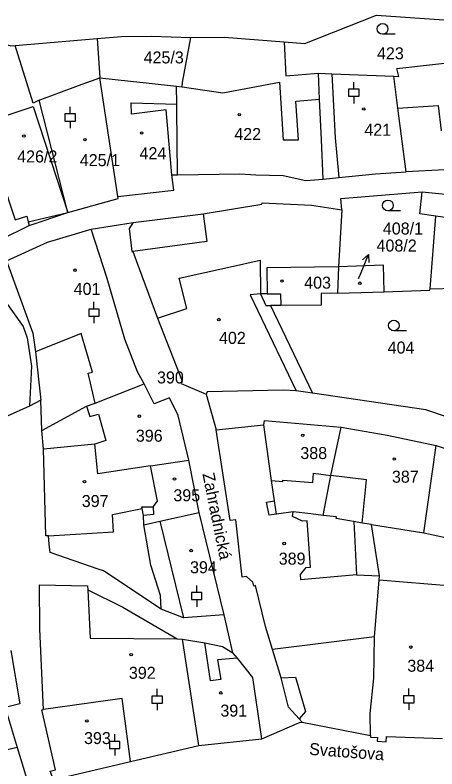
# Model space of a CAD drawing. Extents: x -737240 to -735272, y -1119606 to -1117878.
# Drawn here: x -736084.7 to -736024.9, y -1119478 to -1119371.4 of the extents above; entities that cross this region are included whole.
import ezdxf

# ---------------------------------------------------------------- set-up
doc = ezdxf.new("R2010")
doc.units = 0
for name, color, linetype in [('Level 1', 7, 'Continuous'), ('Level 15', 7, 'Continuous'), ('Level 16', 7, 'Continuous'), ('Level 18', 7, 'Continuous'), ('Level 19', 7, 'Continuous'), ('Level 25', 7, 'Continuous'), ('Level 4', 7, 'Continuous')]:
    doc.layers.add(name, color=color, linetype=linetype)

msp = doc.modelspace()

# ---------------------------------------------------------------- linework, layer by layer
at = {"layer": 'Level 1'}
for p, q in [((-736084.65, -1119375.65), (-736073.07, -1119374.67)), ((-736073.07, -1119374.67), (-736072.68, -1119380.23)), ((-736041.73, -1119379.58), (-736039.83, -1119379.66)), ((-736041.56, -1119383.28), (-736041.73, -1119379.58)), ((-736070.15, -1119397.05), (-736072.68, -1119380.23)), ((-736039.83, -1119379.66), (-736031.06, -1119380.02)), ((-736030.48, -1119384.55), (-736031.06, -1119380.02)), ((-736061.8, -1119383.96), (-736061.83, -1119381.42)), ((-736061.83, -1119381.42), (-736061.04, -1119381.53)), ((-736077.23, -1119399.29), (-736081.29, -1119383.4)), ((-736029.32, -1119393.53), (-736030.48, -1119384.55)), ((-736062.47, -1119393.97), (-736061.69, -1119393.96)), ((-736041.05, -1119394.6), (-736038.82, -1119394.34)), ((-736082.68, -1119401.14), (-736077.23, -1119399.29)), ((-736067.94, -1119400.7), (-736058.04, -1119399.48)), ((-736038.41, -1119398.94), (-736038.9, -1119406.97)), ((-736025.92, -1119410.1), (-736025.11, -1119399.83)), ((-736082.82, -1119400.63), (-736082.68, -1119401.14)), ((-736073.89, -1119401.66), (-736067.94, -1119400.7)), ((-736068.03, -1119404.81), (-736064.52, -1119414.26)), ((-736038.9, -1119406.97), (-736039.04, -1119410.73)), ((-736049, -1119410.79), (-736049.95, -1119410.8)), ((-736039.04, -1119410.73), (-736032.41, -1119410.51)), ((-736047.06, -1119412.43), (-736048.5, -1119412.44)), ((-736048.5, -1119412.44), (-736042.57, -1119424.85)), ((-736081.78, -1119418.99), (-736081.03, -1119425.85)), ((-736073.34, -1119426.29), (-736066.39, -1119423.52)), ((-736057.61, -1119424.98), (-736056.23, -1119430.06)), ((-736042.57, -1119424.85), (-736044.86, -1119424.51)), ((-736081.03, -1119425.85), (-736082.65, -1119426.67)), ((-736080.9, -1119430.13), (-736081.03, -1119425.85)), ((-736074.56, -1119426.69), (-736073.34, -1119426.29)), ((-736082.65, -1119426.67), (-736090.01, -1119429.97)), ((-736080.9, -1119430.13), (-736074.56, -1119426.69)), ((-736056.23, -1119430.06), (-736049.48, -1119429.31)), ((-736039.98, -1119436.48), (-736038.5, -1119429.65)), ((-736080.67, -1119432.79), (-736080.9, -1119430.13)), ((-736073.38, -1119432.07), (-736080.67, -1119432.79)), ((-736026.81, -1119444.6), (-736025.04, -1119432.26)), ((-736025.04, -1119432.26), (-736013.53, -1119436.23)), ((-736065.52, -1119435.13), (-736060.1, -1119434.31)), ((-736058.62, -1119441.71), (-736060.1, -1119434.31)), ((-736041.04, -1119442.14), (-736039.98, -1119436.48)), ((-736047.94, -1119440.09), (-736048.35, -1119437.22)), ((-736047.67, -1119441.96), (-736047.94, -1119440.09)), ((-736066.52, -1119442.18), (-736066.68, -1119441.16)), ((-736066.43, -1119443.48), (-736066.52, -1119442.18)), ((-736064.2, -1119442.97), (-736058.62, -1119441.71)), ((-736055.07, -1119456.2), (-736058.62, -1119441.71)), ((-736045.29, -1119441.63), (-736047.67, -1119441.96)), ((-736066.43, -1119443.48), (-736064.2, -1119442.97)), ((-736035.54, -1119443.22), (-736036.7, -1119443.02)), ((-736034.22, -1119443.45), (-736035.54, -1119443.22)), ((-736034.22, -1119443.45), (-736026.81, -1119444.6)), ((-736033.09, -1119450.68), (-736034.22, -1119443.45)), ((-736026.81, -1119444.6), (-736017.07, -1119446.68)), ((-736033.14, -1119451.24), (-736033.09, -1119450.68)), ((-736033.8, -1119459.33), (-736033.14, -1119451.24)), ((-736033.14, -1119451.24), (-736022.77, -1119452.11)), ((-736060.82, -1119456.62), (-736064, -1119455.39)), ((-736055.07, -1119456.2), (-736060.82, -1119456.62)), ((-736053.87, -1119461.59), (-736055.07, -1119456.2)), ((-736061.74, -1119459.59), (-736060.97, -1119459.67)), ((-736058.67, -1119474.71), (-736060.97, -1119459.67)), ((-736060.97, -1119459.67), (-736057.81, -1119460.16)), ((-736053.2, -1119462.35), (-736053.87, -1119461.59)), ((-736046.99, -1119465.13), (-736048.21, -1119461.12)), ((-736044.03, -1119471.37), (-736044.45, -1119470.92)), ((-736044.03, -1119471.37), (-736034.34, -1119473.29)), ((-736058.67, -1119474.71), (-736049.73, -1119473.75)), ((-736084.37, -1119474.98), (-736089.13, -1119476.09)), ((-736068.32, -1119476.96), (-736058.67, -1119474.71))]:
    msp.add_line(p, q, dxfattribs=at)
for points in [[(-736046.57, -1119375.17), (-736043.65, -1119375.41), (-736033.49, -1119371.37), (-736023.98, -1119372.04), (-736014.53, -1119371.45), (-736013.76, -1119377.04)], [(-736087.52, -1119375.07), (-736085.3, -1119375.7), (-736084.65, -1119375.65)], [(-736073.07, -1119374.67), (-736069.61, -1119374.38), (-736065.36, -1119374.33), (-736059.78, -1119374.52)], [(-736061.04, -1119381.53), (-736060.96, -1119380.9), (-736059.78, -1119374.52)], [(-736059.78, -1119374.52), (-736055.07, -1119374.48), (-736046.57, -1119375.17)], [(-736046.57, -1119375.17), (-736046.35, -1119379.95), (-736041.73, -1119379.58)], [(-736081.29, -1119383.4), (-736082.1, -1119383.85), (-736084.65, -1119375.65)], [(-736031.06, -1119380.02), (-736030.33, -1119380.05), (-736030.61, -1119378.91), (-736013.76, -1119377.04)], [(-736072.68, -1119380.23), (-736068.32, -1119380.7), (-736066.14, -1119380.94), (-736061.83, -1119381.42)], [(-736041.05, -1119394.6), (-736041.3, -1119389.02), (-736041.56, -1119383.28)], [(-736061.69, -1119393.96), (-736061.79, -1119384.61), (-736061.8, -1119383.96)], [(-736030.48, -1119384.55), (-736024.79, -1119384.14), (-736024.37, -1119387.75)], [(-736015.35, -1119393.23), (-736017.32, -1119393.07), (-736018.21, -1119393.1), (-736021.7, -1119393.2), (-736023.88, -1119393.27), (-736029.32, -1119393.53)], [(-736086.6, -1119394.48), (-736084.67, -1119400.35), (-736083.03, -1119399.83), (-736082.82, -1119400.63)], [(-736070.15, -1119397.05), (-736062.22, -1119396.15), (-736062.47, -1119393.97)], [(-736061.69, -1119393.96), (-736052.88, -1119393.85), (-736050.58, -1119393.95), (-736046.73, -1119394.06), (-736043.51, -1119394.77), (-736041.05, -1119394.6)], [(-736038.82, -1119394.34), (-736033.66, -1119393.83), (-736029.32, -1119393.53)], [(-736038.41, -1119398.94), (-736038.55, -1119397.32), (-736027.03, -1119396.36)], [(-736025.11, -1119399.83), (-736027.35, -1119399.5), (-736027.03, -1119396.36)], [(-736027.03, -1119396.36), (-736022.77, -1119396.8), (-736009.67, -1119398.12)], [(-736077.23, -1119399.29), (-736070.11, -1119397.3), (-736070.15, -1119397.05)], [(-736058.04, -1119399.48), (-736049.72, -1119398.12), (-736049.71, -1119397.91), (-736042.73, -1119398.26), (-736038.41, -1119398.94)], [(-736067.94, -1119400.7), (-736068.53, -1119401.55), (-736068.16, -1119404.83), (-736068.03, -1119404.81)], [(-736093.38, -1119406.39), (-736086.72, -1119403.1), (-736082.68, -1119401.14)], [(-736085.92, -1119406.12), (-736080.08, -1119403.47), (-736073.89, -1119401.66)], [(-736066.39, -1119423.52), (-736067.35, -1119421.82), (-736069.12, -1119417.23), (-736071.66, -1119408.61), (-736073.89, -1119401.66)], [(-736085.92, -1119406.12), (-736082.17, -1119416.37), (-736081.78, -1119418.99)], [(-736038.9, -1119406.97), (-736049.03, -1119407.14), (-736049, -1119410.79)], [(-736032.41, -1119410.51), (-736032.53, -1119406.75), (-736038.9, -1119406.97)], [(-736088.59, -1119408.39), (-736083.52, -1119415.42), (-736082.96, -1119417.03), (-736082.38, -1119421.04), (-736082.65, -1119426.67)], [(-736032.41, -1119410.51), (-736025.94, -1119410.3), (-736025.92, -1119410.1)], [(-736025.92, -1119410.1), (-736022.38, -1119409.98), (-736018.9, -1119410.43)], [(-736049.95, -1119410.8), (-736049.17, -1119412.44), (-736048.5, -1119412.44)], [(-736039.04, -1119410.73), (-736041.34, -1119410.74), (-736041.33, -1119412.41), (-736047.06, -1119412.43)], [(-736064.52, -1119414.26), (-736061.03, -1119423.17), (-736061.18, -1119423.5), (-736057.61, -1119424.98)], [(-736060.1, -1119434.31), (-736061.59, -1119428.01), (-736062.81, -1119425.5), (-736064.97, -1119426.34), (-736066.39, -1119423.52)], [(-736044.86, -1119424.51), (-736046.7, -1119424.42), (-736057.46, -1119424.66), (-736057.61, -1119424.98)], [(-736020.68, -1119429.21), (-736026.5, -1119427.23), (-736042.57, -1119424.85)], [(-736049.48, -1119429.31), (-736049.38, -1119428.7), (-736038.5, -1119429.65)], [(-736048.35, -1119437.22), (-736048.64, -1119435.2), (-736049.48, -1119429.31)], [(-736038.5, -1119429.65), (-736032.01, -1119430.78), (-736025.04, -1119432.26)], [(-736048.21, -1119461.12), (-736049.2, -1119457.87), (-736050.65, -1119452.07), (-736050.88, -1119452.13), (-736051.02, -1119451.59), (-736051.92, -1119450.8), (-736052.52, -1119450.87), (-736053.42, -1119442.76), (-736054.24, -1119442.85), (-736056.23, -1119430.06)], [(-736079.93, -1119445.05), (-736080.31, -1119445.01), (-736080.67, -1119432.79)], [(-736065.52, -1119435.13), (-736072.96, -1119436.25), (-736073.38, -1119432.07)], [(-736065.13, -1119440.92), (-736064.52, -1119440.14), (-736065.52, -1119435.13)], [(-736066.68, -1119441.16), (-736066.73, -1119440.93), (-736065.13, -1119440.92)], [(-736041.04, -1119442.14), (-736042.8, -1119441.93), (-736045.29, -1119441.63)], [(-736036.7, -1119443.02), (-736037.35, -1119442.91), (-736039.23, -1119442.58), (-736039.19, -1119442.36), (-736041.04, -1119442.14)], [(-736064, -1119455.39), (-736064.11, -1119453.45), (-736065.44, -1119449.17), (-736066.43, -1119443.48)], [(-736064, -1119455.39), (-736072.14, -1119449.97), (-736072.94, -1119449.73), (-736079.71, -1119447.37), (-736079.88, -1119446.21), (-736079.93, -1119445.05)], [(-736080.68, -1119469.61), (-736081.18, -1119458.22), (-736081.25, -1119451.98), (-736074.41, -1119452.12), (-736074.38, -1119452.65)], [(-736074.38, -1119452.65), (-736069.44, -1119455.11), (-736061.74, -1119459.59)], [(-736034.34, -1119473.29), (-736034.41, -1119470.16), (-736033.9, -1119465.19), (-736033.8, -1119459.33)], [(-736057.81, -1119460.16), (-736055.32, -1119460.71), (-736053.87, -1119461.59)], [(-736085.27, -1119461.24), (-736083.99, -1119468.81), (-736086.1, -1119469.33), (-736084.37, -1119474.98)], [(-736049.73, -1119473.75), (-736051.01, -1119465.06), (-736053.2, -1119462.35)], [(-736044.45, -1119470.92), (-736045.95, -1119469.27), (-736046.99, -1119465.13)], [(-736068.32, -1119476.96), (-736069.54, -1119468.04), (-736080.68, -1119469.61)], [(-736079, -1119480.18), (-736079.73, -1119478.33), (-736078.94, -1119478.12), (-736080.88, -1119469.64), (-736080.68, -1119469.61)], [(-736049.73, -1119473.75), (-736044.4, -1119471.45), (-736044.03, -1119471.37)], [(-736034.34, -1119473.29), (-736034.33, -1119473.53), (-736033.38, -1119473.55), (-736033.39, -1119474.07), (-736032.14, -1119474.17), (-736032.11, -1119473.43), (-736024.17, -1119473.71)], [(-736084.37, -1119474.98), (-736082.69, -1119480.52), (-736080.98, -1119484.97)], [(-736079, -1119480.18), (-736077.13, -1119480.13), (-736077.35, -1119479.08), (-736068.32, -1119476.96)]]:
    msp.add_lwpolyline(points, dxfattribs=at)
at = {"layer": 'Level 16'}
for points in [[(-736036.03, -1119408.61), (-736035.79, -1119408.02), (-736034.653, -1119405.244)], [(-736035.495, -1119405.98), (-736034.653, -1119405.244), (-736034.569, -1119406.359)]]:
    msp.add_lwpolyline(points, dxfattribs=at)
at = {"layer": 'Level 25'}
for p, q in [((-736030.858, -1119374.08), (-736032.64, -1119374.08)), ((-736036.73, -1119381.86), (-736036.73, -1119380.86)), ((-736036.73, -1119382.86), (-736036.73, -1119383.86)), ((-736076.87, -1119385.36), (-736076.87, -1119384.36)), ((-736076.87, -1119386.36), (-736076.87, -1119387.36)), ((-736030.108, -1119399.05), (-736031.89, -1119399.05)), ((-736073.51, -1119412.95), (-736073.51, -1119411.95)), ((-736073.51, -1119413.95), (-736073.51, -1119414.95)), ((-736029.268, -1119416.03), (-736031.05, -1119416.03)), ((-736058.97, -1119453.06), (-736058.97, -1119452.06)), ((-736058.97, -1119454.06), (-736058.97, -1119455.06)), ((-736064.57, -1119467.69), (-736064.57, -1119466.69)), ((-736028.94, -1119467.65), (-736028.94, -1119466.65)), ((-736064.57, -1119468.69), (-736064.57, -1119469.69)), ((-736028.94, -1119468.65), (-736028.94, -1119469.65)), ((-736070.58, -1119474.11), (-736070.58, -1119473.11)), ((-736070.58, -1119475.11), (-736070.58, -1119476.11))]:
    msp.add_line(p, q, dxfattribs=at)
for points in [[(-736037.48, -1119382.86), (-736035.98, -1119382.86), (-736035.98, -1119381.86), (-736037.48, -1119381.86)], [(-736077.62, -1119386.36), (-736076.12, -1119386.36), (-736076.12, -1119385.36), (-736077.62, -1119385.36)], [(-736074.26, -1119413.95), (-736072.76, -1119413.95), (-736072.76, -1119412.95), (-736074.26, -1119412.95)], [(-736059.72, -1119454.06), (-736058.22, -1119454.06), (-736058.22, -1119453.06), (-736059.72, -1119453.06)], [(-736065.32, -1119468.69), (-736063.82, -1119468.69), (-736063.82, -1119467.69), (-736065.32, -1119467.69)], [(-736029.69, -1119468.65), (-736028.19, -1119468.65), (-736028.19, -1119467.65), (-736029.69, -1119467.65)], [(-736071.33, -1119475.11), (-736069.83, -1119475.11), (-736069.83, -1119474.11), (-736071.33, -1119474.11)]]:
    msp.add_lwpolyline(points, close=True, dxfattribs=at)
for centre, major_axis, ratio in [((-736032.64, -1119373.324), (0.764, 0), 0.9894236), ((-736035.31, -1119384.65), (0.18, 0), 0.9848078), ((-736052.93, -1119385.45), (0.18, 0), 0.9848078), ((-736066.76, -1119388.05), (0.18, 0), 0.9848078), ((-736083.45, -1119388.48), (0.18, 0), 0.9848078), ((-736074.79, -1119389), (0.18, 0), 0.9848078), ((-736031.89, -1119398.294), (0.764, 0), 0.9894236), ((-736076.2, -1119407.46), (0.18, 0), 0.9848078), ((-736046.89, -1119408.99), (0.18, 0), 0.9848078), ((-736035.87, -1119409.3), (0.18, 0), 0.9848078), ((-736055.83, -1119414.44), (0.18, 0), 0.9848078), ((-736031.05, -1119415.274), (0.764, 0), 0.9894236), ((-736067.09, -1119428.1), (0.18, 0), 0.9848078), ((-736043.95, -1119430.82), (0.18, 0), 0.9848078), ((-736030.98, -1119434.17), (0.18, 0), 0.9848078), ((-736062.1, -1119437), (0.18, 0), 0.9848078), ((-736074.86, -1119437.37), (0.18, 0), 0.9848078), ((-736046.57, -1119446.12), (0.18, 0), 0.9848078), ((-736059.75, -1119447.12), (0.18, 0), 0.9848078), ((-736028.65, -1119460.77), (0.18, 0), 0.9848078), ((-736068.24, -1119461.85), (0.18, 0), 0.9848078), ((-736055.56, -1119467.25), (0.18, 0), 0.9848078), ((-736074.53, -1119471.22), (0.18, 0), 0.9848078)]:
    msp.add_ellipse(centre, major_axis=major_axis, ratio=ratio, dxfattribs=at)
at = {"layer": 'Level 4'}
for p, q in [((-736082.82, -1119400.63), (-736077.23, -1119399.29)), ((-736064.2, -1119442.97), (-736060.82, -1119456.62)), ((-736036.7, -1119443.02), (-736036.35, -1119450.53)), ((-736036.35, -1119450.53), (-736033.09, -1119450.68)), ((-736033.8, -1119459.33), (-736048.21, -1119461.12))]:
    msp.add_line(p, q, dxfattribs=at)
for points in [[(-736081.29, -1119383.4), (-736075.72, -1119381.35), (-736072.68, -1119380.23)], [(-736039.83, -1119379.66), (-736039.38, -1119388.72), (-736038.82, -1119394.34)], [(-736061.04, -1119381.53), (-736055.26, -1119382.38), (-736047.23, -1119380.86), (-736046.71, -1119389.01), (-736044.54, -1119389.01), (-736044.94, -1119383.53), (-736041.56, -1119383.28)], [(-736062.47, -1119393.97), (-736063.29, -1119384.79), (-736068.2, -1119385.39), (-736068.24, -1119383.77), (-736061.8, -1119383.96)], [(-736086.84, -1119386.04), (-736085.94, -1119385.58), (-736082.12, -1119384.32), (-736077.23, -1119399.29)], [(-736058.04, -1119399.48), (-736057.52, -1119403.41), (-736068.03, -1119404.81)], [(-736016.28, -1119410.77), (-736015.93, -1119407.73), (-736023.83, -1119406.91), (-736023.12, -1119400.12), (-736025.11, -1119399.83)], [(-736064.52, -1119414.26), (-736060.35, -1119412.86), (-736061.47, -1119408.57), (-736054.17, -1119406.97), (-736050, -1119406.06), (-736049.95, -1119410.8)], [(-736049.95, -1119410.8), (-736051.39, -1119410.93), (-736044.86, -1119424.51)], [(-736049, -1119410.79), (-736047.08, -1119410.78), (-736047.06, -1119412.43)], [(-736073.34, -1119426.29), (-736074.34, -1119422.02), (-736073.7, -1119421.87), (-736075.34, -1119416.4), (-736081.78, -1119418.99)], [(-736074.56, -1119426.69), (-736074.09, -1119428.17), (-736072.89, -1119427.82), (-736071.81, -1119431.56), (-736073.38, -1119432.07)], [(-736048.35, -1119437.22), (-736046.77, -1119437.34), (-736046.76, -1119437.18), (-736042.53, -1119437.5), (-736042.43, -1119436.18), (-736039.98, -1119436.48)], [(-736035.54, -1119443.22), (-736034.94, -1119437.11), (-736039.98, -1119436.48)], [(-736047.67, -1119441.96), (-736048.72, -1119442.11), (-736049.08, -1119440.25), (-736047.94, -1119440.09)], [(-736079.93, -1119445.05), (-736070.75, -1119444.49), (-736070.88, -1119442), (-736066.68, -1119441.16)], [(-736065.13, -1119440.92), (-736065.06, -1119442.01), (-736066.52, -1119442.18)], [(-736036.35, -1119450.53), (-736044.22, -1119451.24), (-736044.27, -1119450.52), (-736043.45, -1119449.53), (-736042.83, -1119449.47), (-736043.33, -1119442.89), (-736043.98, -1119442.94), (-736045.38, -1119442.29), (-736045.29, -1119441.63)], [(-736074.38, -1119452.65), (-736074.04, -1119459.52), (-736061.74, -1119459.59)], [(-736053.2, -1119462.35), (-736056.04, -1119462.57), (-736055.56, -1119465.36), (-736057.02, -1119465.54), (-736057.81, -1119460.16)], [(-736046.99, -1119465.13), (-736044.98, -1119465.03), (-736043.54, -1119469.86), (-736044.45, -1119470.92)]]:
    msp.add_lwpolyline(points, dxfattribs=at)

# ---------------------------------------------------------------- texts
at = {"layer": 'Level 15'}
for s, rotation, p in [('Zahradnická', 281.43144, (-736058.163, -1119436.272)), ('Svatošova', 355.75938, (-736043.085, -1119476.003))]:
    msp.add_text(s, height=1.7, rotation=rotation, dxfattribs=at).set_placement(p)
at = {"layer": 'Level 16'}
msp.add_text('408/2', height=1.7, dxfattribs=at).set_placement((-736033.495, -1119404.82))
at = {"layer": 'Level 18'}
for s, p in [('423', (-736033.435, -1119377.63)), ('425/3', (-736066.48, -1119378.21)), ('408/1', (-736032.605, -1119402.41)), ('404', (-736031.925, -1119419.25)), ('390', (-736064.585, -1119423.48))]:
    msp.add_text(s, height=1.7, dxfattribs=at).set_placement(p)
at = {"layer": 'Level 19'}
for s, height, p in [('421', 1.7, (-736035.22, -1119388.45)), ('422', 1.7, (-736053.64, -1119389.05)), ('424', 1.7, (-736067.06, -1119391.76)), ('426/2', 1.7, (-736084.39, -1119392.22)), ('425/1', 1.7, (-736075.52, -1119392.74)), ('403', 1.7, (-736043.74, -1119410.07)), ('401', 1.7, (-736076.39, -1119410.95)), ('408/2', 0.1, (-736035.88, -1119408.61)), ('402', 1.7, (-736055.81, -1119417.88)), ('396', 1.7, (-736067.58, -1119431.72)), ('388', 1.7, (-736044.29, -1119434.17)), ('387', 1.7, (-736031.32, -1119437.52)), ('397', 1.7, (-736075.24, -1119440.96)), ('395', 1.7, (-736062.27, -1119440.15)), ('389', 1.7, (-736047.35, -1119449.11)), ('394', 1.7, (-736059.91, -1119450.33)), ('384', 1.7, (-736029.14, -1119464.26)), ('392', 1.7, (-736068.57, -1119465.26)), ('391', 1.7, (-736055.61, -1119470.61)), ('393', 1.7, (-736074.92, -1119474.49))]:
    msp.add_text(s, height=height, dxfattribs=at).set_placement(p)

doc.saveas('drawing.dxf')
